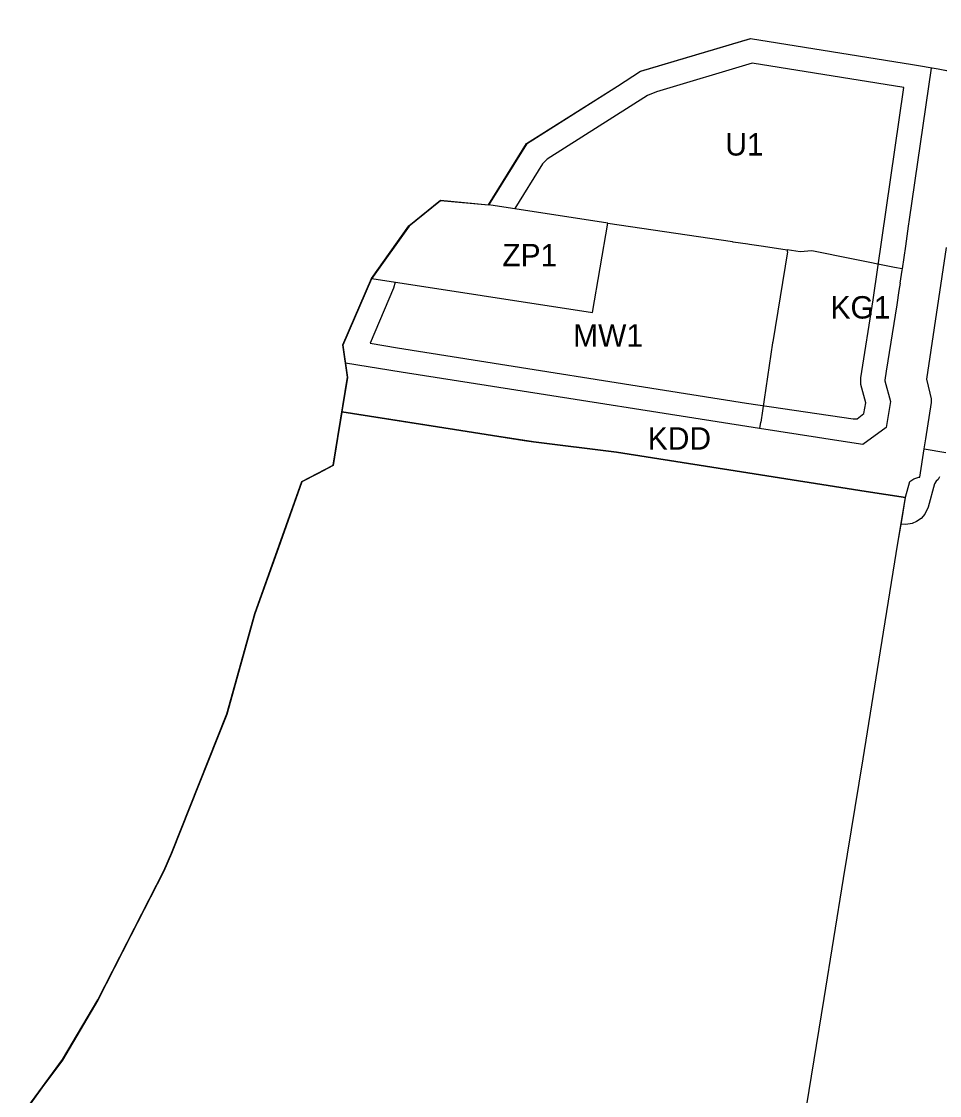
# Model space of a CAD drawing. Extents: x 7428103 to 7431580, y 5545880 to 5549002.
# Drawn here: x 7429568.3 to 7429795.6, y 5548732.6 to 5548998.6 of the extents above; entities that cross this region are included whole.
import ezdxf

# ---------------------------------------------------------------- set-up
doc = ezdxf.new("R2010")
doc.units = 0
for name, color, linetype in [('CZ_L_granica obszaru objętego planem', 7, 'Continuous'), ('CZ_L_linie rozgraniczające tereny o różnym przeznaczeniu oraz różnych warunkach ich zabudowy i zagospodarowania', 7, 'Continuous'), ('CZ_L_maksymalne nieprzekraczalne linie zabudowy', 7, 'Continuous'), ('CZ_L_opisy_linie rozgraniczające tereny o różnym przeznaczeniu oraz różnych warunkach ich zabudowy i zagospodarowania', 7, 'Continuous'), ('CZYŻYNY - REJON ULICY ŚLIWKOWEJ', 7, 'Continuous')]:
    doc.layers.add(name, color=color, linetype=linetype)

msp = doc.modelspace()

# ---------------------------------------------------------------- linework, layer by layer
at = {"layer": 'CZ_L_granica obszaru objętego planem'}
for p, q in [((7429721.52, 5548986.25), (7429748.75, 5548994.36)), ((7429748.75, 5548994.36), (7429788.83, 5548987.94)), ((7429715.87, 5548982.57), (7429721.52, 5548986.25)), ((7429788.83, 5548987.94), (7429795.21, 5548986.84)), ((7429795.21, 5548986.84), (7429804.32, 5548985.03)), ((7429693.33, 5548968.32), (7429715.87, 5548982.57)), ((7429683.94, 5548953.15), (7429693.33, 5548968.32)), ((7429664.23, 5548947.99), (7429672.02, 5548954.28)), ((7429672.02, 5548954.28), (7429683.94, 5548953.15)), ((7429654.92, 5548934.9), (7429664.23, 5548947.99)), ((7429647.86, 5548918.49), (7429654.92, 5548934.9)), ((7429648.99, 5548910.5), (7429647.86, 5548918.49)), ((7429645.43, 5548888.69), (7429648.99, 5548910.5)), ((7429637.72, 5548884.64), (7429645.43, 5548888.69)), ((7429626.09, 5548851.97), (7429637.72, 5548884.64)), ((7429619.16, 5548827.07), (7429626.09, 5548851.97)), ((7429605.45, 5548792.59), (7429619.16, 5548827.07)), ((7429603.56, 5548788.24), (7429605.45, 5548792.59)), ((7429587.18, 5548756.3), (7429603.56, 5548788.24)), ((7429578.43, 5548741.47), (7429587.18, 5548756.3)), ((7429568.3, 5548727.63), (7429578.43, 5548741.47))]:
    msp.add_line(p, q, dxfattribs=at)
at = {"layer": 'CZ_L_linie rozgraniczające tereny o różnym przeznaczeniu oraz różnych warunkach ich zabudowy i zagospodarowania'}
for p, q in [((7429793.53, 5548987.03), (7429788.07, 5548949.55)), ((7429713.48, 5548948.62), (7429684.01, 5548953.14)), ((7429709.65, 5548926.46), (7429713.48, 5548948.62)), ((7429713.48, 5548948.62), (7429744.32, 5548944.05)), ((7429788.06, 5548949.53), (7429787.82, 5548947.87)), ((7429788.07, 5548949.55), (7429788.06, 5548949.54)), ((7429788.06, 5548949.54), (7429788.06, 5548949.53)), ((7429787.82, 5548947.87), (7429787.1, 5548942.91)), ((7429744.32, 5548944.05), (7429744.31, 5548943.97)), ((7429744.31, 5548943.97), (7429744.45, 5548944.04)), ((7429744.45, 5548944.04), (7429748.12, 5548943.49)), ((7429748.12, 5548943.49), (7429748.49, 5548943.44)), ((7429748.49, 5548943.44), (7429751.96, 5548942.92)), ((7429751.96, 5548942.92), (7429757.88, 5548942.04)), ((7429757.94, 5548941.51), (7429754.33, 5548919.21)), ((7429757.88, 5548942.04), (7429757.81, 5548941.59)), ((7429757.81, 5548941.59), (7429757.86, 5548941.5)), ((7429757.86, 5548941.5), (7429757.89, 5548941.52)), ((7429761.1, 5548941.56), (7429757.88, 5548942.04)), ((7429757.89, 5548941.52), (7429757.94, 5548941.51)), ((7429763.95, 5548941.74), (7429761.1, 5548941.56)), ((7429784.41, 5548937.63), (7429763.95, 5548941.74)), ((7429787.1, 5548942.91), (7429786.28, 5548937.32)), ((7429792.42, 5548910.02), (7429797.29, 5548942.62)), ((7429786.28, 5548937.32), (7429784.41, 5548937.63)), ((7429786.23, 5548936.95), (7429785.77, 5548933.8)), ((7429786.28, 5548937.32), (7429786.23, 5548936.95)), ((7429654.99, 5548934.89), (7429709.65, 5548926.46)), ((7429785.78, 5548933.78), (7429785.51, 5548931.94)), ((7429785.77, 5548933.8), (7429785.78, 5548933.78)), ((7429785.51, 5548931.94), (7429784.99, 5548928.36)), ((7429784.99, 5548928.36), (7429782.37, 5548911.97)), ((7429754.22, 5548919.02), (7429751.32, 5548899.33)), ((7429754.33, 5548919.21), (7429754.22, 5548919.02)), ((7429662.27, 5548911.71), (7429648.5, 5548913.93)), ((7429684.9, 5548908.2), (7429662.27, 5548911.71)), ((7429782.37, 5548911.97), (7429782.02, 5548909.74)), ((7429782.02, 5548909.74), (7429782.06, 5548909.6)), ((7429782.06, 5548909.6), (7429783.45, 5548904.45)), ((7429793.28, 5548906.49), (7429792.42, 5548910.02)), ((7429747.82, 5548898.3), (7429684.9, 5548908.2)), ((7429793.55, 5548905.11), (7429793.28, 5548906.49)), ((7429783.45, 5548904.45), (7429782.35, 5548897.99)), ((7429792.14, 5548895.18), (7429793.58, 5548904.19)), ((7429793.58, 5548904.19), (7429793.55, 5548905.11)), ((7429647.62, 5548901.93), (7429677.1, 5548897.29)), ((7429750.97, 5548897.8), (7429747.82, 5548898.3)), ((7429751.24, 5548899.34), (7429750.97, 5548897.8)), ((7429751.32, 5548899.33), (7429751.24, 5548899.34)), ((7429782.35, 5548897.99), (7429776.54, 5548893.77)), ((7429677.1, 5548897.29), (7429692.72, 5548894.83)), ((7429765.33, 5548895.54), (7429750.97, 5548897.8)), ((7429768.53, 5548895.04), (7429765.33, 5548895.54)), ((7429692.72, 5548894.83), (7429695.07, 5548894.46)), ((7429695.07, 5548894.46), (7429695.07, 5548894.46)), ((7429695.07, 5548894.46), (7429715.61, 5548891.92)), ((7429776.54, 5548893.77), (7429768.53, 5548895.04)), ((7429790.68, 5548885.72), (7429791.76, 5548892.74)), ((7429791.74, 5548892.75), (7429792.14, 5548895.18)), ((7429791.76, 5548892.74), (7429791.74, 5548892.75)), ((7429791.76, 5548892.74), (7429797.15, 5548891.83)), ((7429715.61, 5548891.92), (7429715.61, 5548891.92)), ((7429715.61, 5548891.92), (7429746.5, 5548887.05)), ((7429788.24, 5548884.61), (7429789.18, 5548885.29)), ((7429789.18, 5548885.29), (7429790.44, 5548885.68)), ((7429790.44, 5548885.68), (7429790.68, 5548885.72)), ((7429777.39, 5548882.19), (7429777.39, 5548882.19)), ((7429777.39, 5548882.19), (7429787.12, 5548880.67)), ((7429787.14, 5548880.77), (7429788.24, 5548884.61))]:
    msp.add_line(p, q, dxfattribs=at)
for points in [[(7429806.72, 5548998.57), (7429804.33, 5548984.92), (7429795.22, 5548986.74), (7429788.84, 5548987.84), (7429748.76, 5548994.26), (7429721.53, 5548986.15), (7429715.88, 5548982.47), (7429693.34, 5548968.21), (7429683.95, 5548953.05), (7429672.03, 5548954.18), (7429664.24, 5548947.89), (7429654.93, 5548934.8), (7429647.87, 5548918.39), (7429649, 5548910.4), (7429647.62, 5548901.93)], [(7429746.5, 5548887.05), (7429777.39, 5548882.19), (7429777.39, 5548882.19)], [(7429763.06, 5548673.06), (7429763.11, 5548673.05), (7429763.26, 5548673.46), (7429759.07, 5548677.72), (7429754.88, 5548681.98), (7429754.88, 5548681.98), (7429758.28, 5548702.89), (7429762.63, 5548729.74), (7429762.63, 5548729.74), (7429766.98, 5548756.58), (7429771.8, 5548786.29), (7429776.62, 5548815.99), (7429780.95, 5548842.67), (7429785.27, 5548869.36), (7429787.15, 5548880.67)], [(7429787.15, 5548880.67), (7429787.12, 5548880.67), (7429787.14, 5548880.77)]]:
    msp.add_lwpolyline(points, dxfattribs=at)
at = {"layer": 'CZ_L_maksymalne nieprzekraczalne linie zabudowy'}
for points in [[(7429660.84, 5548933.97), (7429660.43, 5548932.53), (7429654.58, 5548918.93), (7429661.35, 5548917.72), (7429747.74, 5548904.04), (7429774.22, 5548900.2), (7429775.14, 5548900.17), (7429776.86, 5548901.48), (7429777.31, 5548904.12), (7429776.11, 5548908.7), (7429776.05, 5548910.31), (7429779.11, 5548929.61), (7429786.76, 5548982.2), (7429749.15, 5548988.22), (7429725.47, 5548981.17), (7429723.29, 5548980.26), (7429698.46, 5548964.47), (7429697.29, 5548963.32), (7429690.44, 5548952.25)], [(7429795.55, 5548885.79), (7429795.23, 5548885.12), (7429794.73, 5548884.73), (7429794.32, 5548884.07), (7429792.76, 5548878.28), (7429791.91, 5548876.53), (7429790.99, 5548875.51), (7429789.89, 5548874.74), (7429788.76, 5548874.26), (7429787.26, 5548874), (7429786.06, 5548874.1)]]:
    msp.add_lwpolyline(points, dxfattribs=at)
at = {"layer": 'CZYŻYNY - REJON ULICY ŚLIWKOWEJ'}
for points in [[(7429762.63, 5548729.74), (7429766.98, 5548756.58), (7429771.8, 5548786.29), (7429776.62, 5548815.99), (7429780.95, 5548842.67), (7429785.27, 5548869.36), (7429786.21, 5548875.01), (7429787.15, 5548880.67), (7429782.27, 5548881.43), (7429777.39, 5548882.19), (7429746.5, 5548887.05), (7429715.61, 5548891.92), (7429695.07, 5548894.46), (7429684.91, 5548896.06), (7429677.1, 5548897.29), (7429662.36, 5548899.61), (7429647.62, 5548901.93), (7429647.59, 5548901.75), (7429646.53, 5548895.26), (7429645.44, 5548888.59), (7429641.58, 5548886.56), (7429637.73, 5548884.53)], [(7429637.73, 5548884.53), (7429631.92, 5548868.2), (7429626.1, 5548851.87), (7429622.63, 5548839.42), (7429619.17, 5548826.97), (7429612.32, 5548809.73), (7429605.46, 5548792.48), (7429603.57, 5548788.13), (7429595.38, 5548772.17), (7429587.19, 5548756.2), (7429582.82, 5548748.79), (7429578.44, 5548741.37), (7429573.38, 5548734.45)], [(7429573.38, 5548734.45), (7429570.63, 5548730.7)]]:
    msp.add_lwpolyline(points, dxfattribs=at)

# ---------------------------------------------------------------- texts
at = {"layer": 'CZ_L_opisy_linie rozgraniczające tereny o różnym przeznaczeniu oraz różnych warunkach ich zabudowy i zagospodarowania'}
for s, p in [('U1', (7429742.53, 5548965.37)), ('ZP1', (7429687.32, 5548937.94)), ('KG1', (7429768.57, 5548925)), ('MW1', (7429704.86, 5548918.05)), ('KDD', (7429723.34, 5548892.53))]:
    msp.add_text(s, height=5.549, dxfattribs=at).set_placement(p)

doc.saveas('drawing.dxf')
